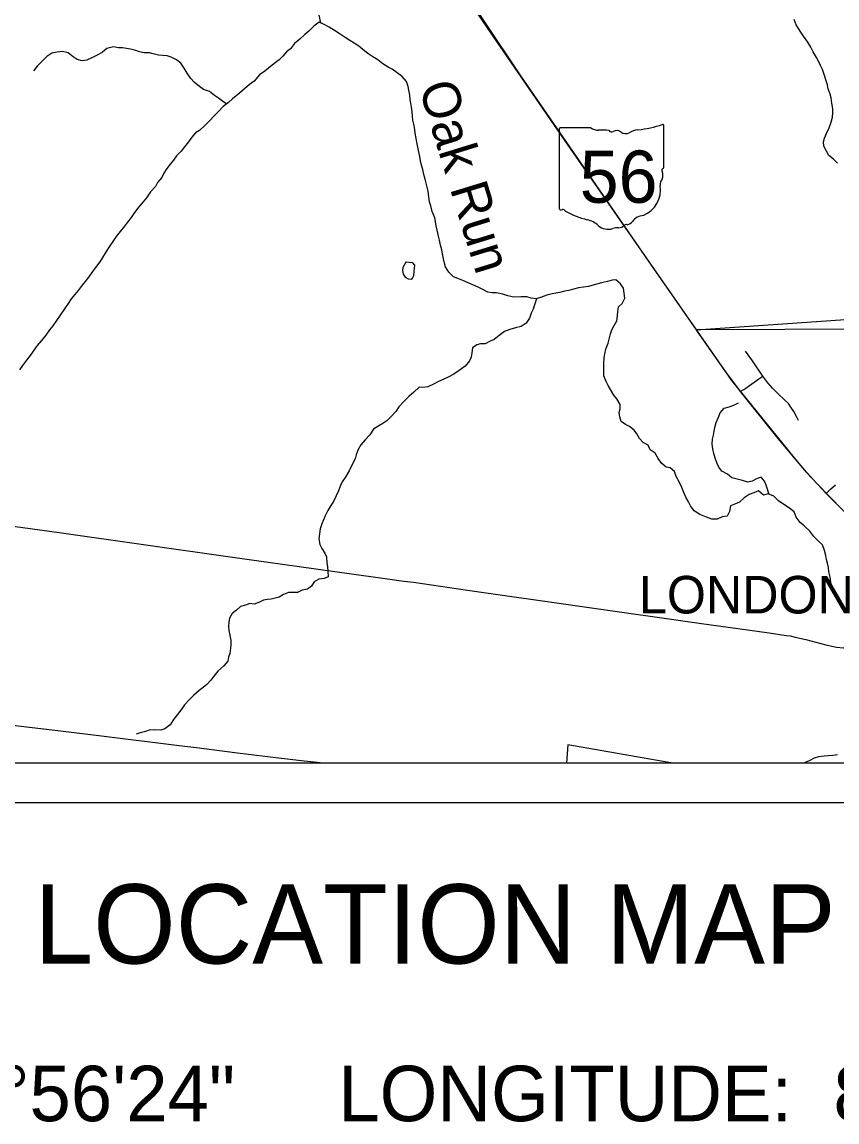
# Model space of a CAD drawing. Extents: x 0 to 36.5, y 0 to 25.3.
# Drawn here: x 4.396 to 6.451, y 13.194 to 15.97 of the extents above; entities that cross this region are included whole.
import ezdxf

# ---------------------------------------------------------------- set-up
doc = ezdxf.new("R2010")
doc.units = 0
for name, color, linetype in [('Default', 7, 'Continuous'), ('DV_X_Township_Line', 7, 'Continuous'), ('GM_X_City_Street', 7, 'Continuous'), ('GM_X_Corporation_Text', 7, 'Continuous'), ('GM_X_County_Road', 7, 'Continuous'), ('GM_X_Minor_Lake', 7, 'Continuous'), ('GM_X_Minor_River', 7, 'Continuous'), ('GM_X_Minor_River_Text', 7, 'Continuous'), ('GM_X_Rail_Line', 7, 'Continuous'), ('GM_X_State_Location', 7, 'Continuous'), ('GM_X_State_Route', 7, 'Continuous'), ('GM_X_State_Shield', 7, 'Continuous'), ('SH_Cut_Line', 7, 'Continuous'), ('SH_Data', 7, 'Continuous'), ('SH_Text', 7, 'Continuous')]:
    doc.layers.add(name, color=color, linetype=linetype)

msp = doc.modelspace()

# ---------------------------------------------------------------- linework, layer by layer
at = {"layer": 'Default'}
msp.add_lwpolyline([(5.7689, 14.1), (6.0321, 14.1), (5.7728, 14.1454)], close=True, dxfattribs=at)
at = {"layer": 'DV_X_Township_Line'}
msp.add_lwpolyline([(2.1, 16.2788), (2.1, 14.1), (8.9, 14.1), (8.9, 14.8674), (8.5228, 15.0526), (8.0723, 15.2737), (7.8139, 15.4027), (7.7814, 15.4189), (7.7552, 15.432), (7.703, 15.458), (6.8419, 15.8878), (6.6079, 15.9978), (5.1383, 16.6527), (4.8891, 16.7511), (4.0938, 16.595), (2.4938, 16.3413), (2.1039, 16.2931)], close=True, dxfattribs=at)
at = {"layer": 'GM_X_City_Street'}
for points in [[(6.354, 14.964), (6.3492, 14.9741), (6.342, 14.9872), (6.335, 14.9979), (6.3285, 15.0068), (6.3199, 15.0158), (6.3019, 15.0326), (6.2886, 15.0454), (6.2767, 15.0595), (6.2645, 15.0761), (6.2382, 15.1149), (6.2203, 15.1387)], [(6.2068, 15.0375), (6.2163, 15.0426), (6.2217, 15.046), (6.2308, 15.0522), (6.2541, 15.0694), (6.2645, 15.0761)], [(6.4241, 14.7802), (6.435, 14.7912), (6.4473, 14.8016)]]:
    msp.add_lwpolyline(points, dxfattribs=at)
at = {"layer": 'GM_X_County_Road'}
for points in [[(4.2393, 14.7169), (4.3059, 14.707), (4.4899, 14.6813), (4.9211, 14.6198), (5.227, 14.5775), (5.3061, 14.5659), (5.3593, 14.5586), (5.3831, 14.556), (5.5195, 14.5361), (6.104, 14.453), (6.2799, 14.4286), (6.3234, 14.4219), (6.333, 14.4203), (6.3453, 14.4176)], [(6.3453, 14.4176), (6.3727, 14.4112), (6.4231, 14.3979), (6.4497, 14.3921), (6.4678, 14.3903), (6.4858, 14.3904), (6.5038, 14.3924), (6.61, 14.4085)]]:
    msp.add_lwpolyline(points, dxfattribs=at)
at = {"layer": 'GM_X_Minor_Lake'}
for points in [[(5.3636, 15.3633), (5.3568, 15.3504), (5.3556, 15.3424), (5.3571, 15.3337), (5.362, 15.3257), (5.3703, 15.3215), (5.3791, 15.3207), (5.3805, 15.3233)], [(5.3805, 15.3233), (5.384, 15.3302), (5.3848, 15.3393), (5.386, 15.3476), (5.3868, 15.3564), (5.3815, 15.3621), (5.372, 15.3629), (5.3636, 15.3633)]]:
    msp.add_lwpolyline(points, dxfattribs=at)
at = {"layer": 'GM_X_Minor_River'}
for points in [[(5.4489, 15.4193), (5.4467, 15.4296), (5.443, 15.4441), (5.4401, 15.4555), (5.439, 15.4661), (5.4368, 15.4756), (5.4305, 15.4917), (5.4272, 15.5054), (5.4239, 15.5156), (5.4221, 15.5282), (5.4207, 15.5426), (5.4174, 15.5533), (5.4152, 15.5628), (5.4126, 15.5727), (5.4097, 15.5849), (5.4068, 15.5975), (5.4031, 15.6082), (5.4009, 15.6192), (5.3995, 15.6302), (5.3958, 15.6451), (5.3929, 15.6622), (5.3904, 15.6759), (5.3878, 15.6888), (5.3868, 15.6987), (5.3842, 15.7117), (5.3817, 15.7219), (5.381, 15.7318), (5.3799, 15.7432), (5.3781, 15.7546), (5.3763, 15.7645), (5.3753, 15.7744), (5.3742, 15.7847), (5.3713, 15.7973), (5.3695, 15.8068), (5.3658, 15.8197), (5.3545, 15.8324), (5.3421, 15.8412), (5.3296, 15.8508), (5.3194, 15.8555), (5.3062, 15.8643), (5.2937, 15.8739), (5.2805, 15.882), (5.2707, 15.8886), (5.2609, 15.8959), (5.2454, 15.9085), (5.2337, 15.9159), (5.2227, 15.9228), (5.211, 15.9305), (5.1986, 15.9393), (5.1838, 15.9482), (5.1706, 15.9567), (5.1585, 15.9632), (5.1452, 15.9694), (5.1322, 15.9589), (5.1192, 15.9469), (5.1093, 15.9378), (5.097, 15.9262), (5.0836, 15.9153), (5.0728, 15.9024), (5.0629, 15.8942), (5.0541, 15.8836), (5.0445, 15.8746), (5.0345, 15.867), (5.0185, 15.8539), (5.0081, 15.846), (4.9951, 15.8362), (4.9813, 15.8204), (4.9702, 15.8121), (4.9572, 15.8012), (4.9446, 15.7903), (4.9273, 15.7757), (4.9166, 15.7666), (4.9032, 15.7565), (4.8913, 15.7437), (4.8814, 15.7335), (4.8702, 15.7214), (4.8568, 15.7086), (4.8438, 15.6958), (4.8339, 15.6902), (4.8243, 15.6793), (4.8162, 15.6676), (4.8055, 15.6551), (4.7974, 15.6434), (4.7859, 15.6321), (4.7782, 15.6208), (4.7697, 15.6106), (4.7613, 15.6), (4.7536, 15.5879), (4.7489, 15.5773), (4.7382, 15.5649), (4.7324, 15.5543), (4.7201, 15.5415), (4.7105, 15.5264), (4.702, 15.5162), (4.6905, 15.5034), (4.6801, 15.489), (4.6717, 15.4766), (4.6624, 15.4645), (4.6547, 15.4547), (4.644, 15.4411), (4.6336, 15.4287)], [(5.1495, 15.9675), (5.1458, 15.9869)], [(6.4521, 15.6131), (6.442, 15.6238), (6.4303, 15.6331), (6.4243, 15.6434), (6.4183, 15.6563), (6.4169, 15.6674), (6.4196, 15.6768), (6.4243, 15.6882), (6.4316, 15.7026), (6.4363, 15.717), (6.4399, 15.7299), (6.4411, 15.7401), (6.4404, 15.7508), (6.4383, 15.7652), (6.4365, 15.7781), (6.4339, 15.788), (6.4287, 15.8014), (6.4273, 15.8109), (6.4232, 15.8239), (6.4199, 15.8349), (6.4143, 15.8501), (6.4095, 15.8597), (6.4054, 15.8692), (6.3994, 15.8799), (6.3908, 15.8941), (6.3856, 15.9059), (6.3773, 15.9192), (6.3668, 15.9338), (6.3597, 15.9437), (6.3545, 15.9533), (6.3485, 15.9628), (6.3429, 15.9758)], [(4.9119, 15.7631), (4.9049, 15.7675), (4.892, 15.7775), (4.8818, 15.7844), (4.8686, 15.794), (4.8542, 15.7995), (4.8436, 15.8068), (4.8301, 15.8179), (4.8222, 15.8275), (4.8128, 15.8405), (4.8053, 15.8535), (4.7963, 15.8657), (4.7857, 15.8741), (4.7725, 15.8811), (4.7623, 15.8846), (4.7513, 15.8855), (4.7403, 15.8863), (4.727, 15.8895), (4.7175, 15.8918), (4.7046, 15.8923), (4.6928, 15.8947), (4.6834, 15.8974), (4.6701, 15.9014), (4.6595, 15.903), (4.6492, 15.9046), (4.6397, 15.9047), (4.6272, 15.9071), (4.6101, 15.9026), (4.599, 15.8932), (4.5871, 15.8865), (4.5738, 15.8798), (4.56, 15.8738), (4.5475, 15.8713), (4.535, 15.8748), (4.5248, 15.8821), (4.5123, 15.8921), (4.4983, 15.8956), (4.4846, 15.8935), (4.4713, 15.8909), (4.4587, 15.8823), (4.448, 15.8721), (4.4341, 15.8582), (4.4253, 15.8465)], [(4.6336, 15.4287), (4.6271, 15.4181), (4.6163, 15.4022), (4.6082, 15.3909), (4.5993, 15.3754), (4.5928, 15.3648), (4.5816, 15.3501), (4.5739, 15.3399), (4.5651, 15.327), (4.5551, 15.315), (4.5478, 15.3052), (4.5378, 15.2919), (4.5293, 15.2818), (4.5201, 15.2708), (4.5128, 15.2595), (4.5036, 15.2455), (4.4924, 15.2297), (4.4828, 15.2168), (4.4736, 15.2028), (4.4659, 15.1927), (4.4562, 15.1791), (4.4451, 15.1662), (4.4344, 15.153), (4.4247, 15.1387), (4.417, 15.1285), (4.4078, 15.116), (4.3971, 15.1032), (4.3901, 15.0922)], [(6.1799, 14.7348), (6.1741, 14.7227), (6.1619, 14.7213), (6.149, 14.7153), (6.136, 14.715), (6.1224, 14.7205), (6.105, 14.7271), (6.0914, 14.7359), (6.082, 14.7486), (6.0764, 14.7585), (6.0712, 14.7688), (6.0652, 14.7825), (6.0596, 14.7951), (6.0533, 14.8092), (6.0454, 14.8226), (6.0414, 14.8355), (6.0304, 14.8444), (6.0202, 14.8464), (6.0092, 14.8556), (5.9999, 14.8682), (5.9928, 14.8819), (5.9799, 14.89), (5.9747, 14.9022), (5.9622, 14.9084), (5.9536, 14.9184), (5.9465, 14.9306), (5.9401, 14.9401), (5.928, 14.949), (5.9182, 14.9536), (5.9072, 14.9617), (5.9039, 14.9731), (5.9021, 14.9842), (5.9041, 14.9936), (5.9042, 15.0043), (5.8959, 15.0184), (5.8888, 15.028), (5.8798, 15.0425), (5.8738, 15.0528), (5.869, 15.0623), (5.8634, 15.0764), (5.8631, 15.0859), (5.8633, 15.108), (5.8638, 15.1228), (5.867, 15.1368), (5.8693, 15.1467), (5.8744, 15.1592), (5.8775, 15.1728), (5.8799, 15.1827), (5.8834, 15.1929), (5.8892, 15.2042), (5.8958, 15.216), (5.8978, 15.2285), (5.8987, 15.2391), (5.9003, 15.2509), (5.9098, 15.2592), (5.9161, 15.2728), (5.9143, 15.2857), (5.9132, 15.2983), (5.9057, 15.3086), (5.8937, 15.3189), (5.8842, 15.3183), (5.8723, 15.3149), (5.8575, 15.3117), (5.848, 15.3087), (5.8385, 15.3061), (5.8247, 15.3024), (5.8122, 15.3007), (5.7996, 15.2992), (5.7867, 15.2952), (5.7753, 15.2922), (5.7642, 15.2901), (5.752, 15.2875), (5.7425, 15.2853), (5.733, 15.2839), (5.7193, 15.2802), (5.706, 15.275), (5.6923, 15.2713), (5.6801, 15.2729), (5.6695, 15.2761), (5.6551, 15.2762), (5.6361, 15.2756), (5.6216, 15.2784), (5.6084, 15.283), (5.5928, 15.2862), (5.5818, 15.2863), (5.5708, 15.2883), (5.5568, 15.2956), (5.5466, 15.3007), (5.533, 15.3065), (5.5213, 15.3112), (5.5076, 15.317), (5.4955, 15.3228), (5.4845, 15.3263), (5.4721, 15.3386), (5.4642, 15.3515), (5.4617, 15.3614), (5.4591, 15.3717), (5.4566, 15.3847), (5.4547, 15.3949), (5.4518, 15.4064), (5.4489, 15.4193)], [(5.6932, 15.2715), (5.6887, 15.2558), (5.6848, 15.2451), (5.6802, 15.2349), (5.6755, 15.2224), (5.6674, 15.21), (5.6544, 15.2013), (5.6403, 15.1977), (5.6262, 15.1936), (5.6125, 15.1888), (5.5995, 15.179), (5.5869, 15.1689), (5.5769, 15.1644), (5.5643, 15.1573), (5.5526, 15.1578), (5.543, 15.1552), (5.5323, 15.1473), (5.5303, 15.1348), (5.5287, 15.1242), (5.5248, 15.1143), (5.5137, 15.1015), (5.4984, 15.0906), (5.485, 15.0809), (5.4705, 15.0734), (5.4595, 15.0685), (5.4461, 15.0622), (5.4335, 15.0562), (5.4198, 15.0491), (5.4068, 15.0477), (5.3973, 15.0478), (5.3839, 15.0354), (5.3713, 15.0245), (5.359, 15.012), (5.3467, 14.9985), (5.3387, 14.9864), (5.3272, 14.9739), (5.3157, 14.9634), (5.3061, 14.9563), (5.2958, 14.951), (5.2828, 14.942), (5.2732, 14.9281), (5.2617, 14.9152), (5.2505, 14.9028), (5.2428, 14.8892), (5.2385, 14.8775), (5.2362, 14.8672), (5.2288, 14.8528), (5.2211, 14.8373), (5.2126, 14.8226), (5.2037, 14.8094), (5.1987, 14.7988), (5.194, 14.7863), (5.1882, 14.7742), (5.1816, 14.7598), (5.1747, 14.7496), (5.167, 14.7367), (5.1608, 14.7235), (5.1562, 14.7137), (5.1519, 14.7034), (5.1484, 14.6909), (5.146, 14.678), (5.1447, 14.6651), (5.1469, 14.6514), (5.1525, 14.6415), (5.1596, 14.6293), (5.1637, 14.6198), (5.1651, 14.6053), (5.1665, 14.5954), (5.1675, 14.5829), (5.1682, 14.5692), (5.1583, 14.5651), (5.1449, 14.5633), (5.1327, 14.5566), (5.1258, 14.546), (5.1159, 14.5389), (5.1025, 14.5363), (5.0907, 14.53), (5.0679, 14.5302), (5.0557, 14.5253), (5.045, 14.5186), (5.0343, 14.516), (5.0244, 14.5134), (5.0149, 14.5124), (5.005, 14.5106), (4.9951, 14.5053), (4.9818, 14.5009), (4.9704, 14.5021), (4.9601, 14.4984), (4.9471, 14.4944), (4.9368, 14.4857), (4.9265, 14.4767), (4.9192, 14.4657), (4.9179, 14.4559), (4.9171, 14.4441), (4.9177, 14.4338), (4.9203, 14.4228), (4.9228, 14.4091), (4.9227, 14.3992), (4.9223, 14.3897), (4.9203, 14.3761), (4.9171, 14.3666)], [(6.279, 14.7787), (6.2758, 14.7909), (6.2724, 14.8008), (6.2683, 14.8111), (6.2597, 14.8211), (6.2502, 14.8181), (6.2376, 14.811), (6.2265, 14.8088), (6.2129, 14.8124), (6.1992, 14.8163), (6.186, 14.8198), (6.1747, 14.8283), (6.1607, 14.8364), (6.1535, 14.846), (6.1487, 14.8559), (6.1442, 14.8688), (6.1409, 14.8806), (6.1384, 14.8924), (6.1362, 14.9042), (6.1374, 14.9168), (6.1394, 14.927), (6.1418, 14.9376), (6.1442, 14.9498), (6.1469, 14.9592), (6.152, 14.9725), (6.157, 14.9838), (6.167, 14.9951), (6.1792, 14.9988), (6.191, 15.0025), (6.2028, 15.0085)], [(6.453, 14.5113), (6.4467, 14.5243), (6.443, 14.5353), (6.4381, 14.5456), (6.4359, 14.5559), (6.4337, 14.5684), (6.4308, 14.5825), (6.4294, 14.5932), (6.4272, 14.6038), (6.425, 14.6137), (6.4232, 14.6236), (6.4199, 14.6362), (6.4143, 14.6507), (6.4045, 14.6595), (6.3929, 14.671), (6.3823, 14.6848), (6.3688, 14.6982), (6.3586, 14.7066), (6.3481, 14.72), (6.3429, 14.7334), (6.3316, 14.743), (6.3172, 14.7522), (6.3036, 14.7618), (6.2919, 14.7733), (6.2779, 14.7791), (6.2661, 14.7758), (6.2533, 14.7862), (6.2419, 14.7814), (6.2297, 14.7777), (6.2174, 14.7687), (6.2052, 14.7581), (6.1956, 14.754), (6.1827, 14.7488), (6.1799, 14.7348)], [(4.9171, 14.3666), (4.9148, 14.3571), (4.9048, 14.345), (4.8899, 14.3315), (4.8795, 14.319), (4.8726, 14.3088), (4.8622, 14.2983), (4.8526, 14.2904), (4.8427, 14.2825), (4.8293, 14.2708), (4.8186, 14.2599), (4.8063, 14.2467), (4.799, 14.2365), (4.7882, 14.2226), (4.7786, 14.2094), (4.7697, 14.1958), (4.7564, 14.1864), (4.7461, 14.183), (4.7301, 14.1839), (4.7168, 14.1825), (4.7073, 14.1792), (4.694, 14.1763), (4.6837, 14.1726)], [(6.4522, 14.1207), (6.4404, 14.1186), (6.4301, 14.1175), (6.4187, 14.1168), (6.4043, 14.1158), (6.3932, 14.1117), (6.381, 14.1054), (6.3711, 14.1013), (6.3689, 14.1)]]:
    msp.add_lwpolyline(points, dxfattribs=at)
at = {"layer": 'GM_X_Rail_Line'}
for points in [[(4.8132, 17.3633), (4.8184, 17.2699), (5.1178, 16.6892), (5.2481, 16.4408), (5.283, 16.3883), (5.6533, 15.8339), (5.9752, 15.3666), (6.1855, 15.065), (6.3543, 14.8564), (6.3992, 14.8058), (6.6962, 14.5011), (6.7726, 14.421), (6.8941, 14.2837), (7.0545, 14.1)], [(2.9959, 14.3635), (3.2993, 14.3271), (3.4345, 14.31), (3.6331, 14.2857), (3.7599, 14.2703), (3.8768, 14.2559), (3.9653, 14.2449), (4.0847, 14.2307), (4.1319, 14.225), (4.2195, 14.2143), (4.28, 14.2068), (4.3249, 14.2011), (4.3358, 14.1998), (4.4011, 14.1918), (4.4931, 14.1806), (4.5963, 14.1681), (4.7925, 14.1443), (4.836, 14.139), (4.9328, 14.1267), (5.0153, 14.1165), (5.1077, 14.1057), (5.1561, 14.1)]]:
    msp.add_lwpolyline(points, dxfattribs=at)
at = {"layer": 'GM_X_State_Route'}
for p, q in [((6.0961, 15.1927), (6.0988, 15.1888)), ((6.4276, 14.7766), (6.4617, 14.7421))]:
    msp.add_line(p, q, dxfattribs=at)
for points in [[(5.2509, 16.4373), (5.2534, 16.4329), (5.5332, 16.0079), (5.5924, 15.9207), (5.7648, 15.6702), (6.0961, 15.1927)], [(6.0988, 15.1888), (6.1715, 15.084), (6.1898, 15.06)], [(6.1898, 15.06), (6.2068, 15.0375), (6.3021, 14.9187), (6.3457, 14.8663), (6.3738, 14.8336), (6.4036, 14.8016), (6.4241, 14.7802), (6.4276, 14.7766)]]:
    msp.add_lwpolyline(points, dxfattribs=at)
at = {"layer": 'GM_X_State_Shield'}
for p, q in [((5.7509, 15.6995), (5.7509, 15.4994)), ((5.8307, 15.703), (5.7535, 15.703)), ((6.0145, 15.6032), (6.0145, 15.7079)), ((6.0145, 15.6033), (6.0145, 15.6032))]:
    msp.add_line(p, q, dxfattribs=at)
for centre, radius, start, end in [((5.9206, 15.9758), 0.2796, 275.8445, 288.9065), ((6.0116, 15.7084), 0.00294, 351.8621, 97.738), ((5.7539, 15.6999), 0.00305, 98.1301, 188.1301), ((5.8491, 15.7262), 0.0296, 231.6195, 271.1119), ((5.8589, 15.5906), 0.1064, 80.4867, 94.9883), ((5.8831, 15.701), 0.00855, 219.7921, 297.1024), ((5.8956, 15.6779), 0.0178, 54.4667, 119.1411), ((5.9185, 15.7096), 0.0214, 233.8562, 294.8282), ((5.9563, 15.6418), 0.0563, 97.3462, 120.7689), ((6.0114, 15.6028), 0.00314, 289.6038, 7.7341), ((6.0251, 15.5594), 0.0198, 136.8065, 186.9296), ((6.0139, 15.5955), 0.00454, 107.944, 210.337), ((5.985, 15.5823), 0.0273, 340.033, 23.6496), ((5.9363, 15.5461), 0.0699, 292.3089, 8.9858), ((5.7539, 15.499), 0.00308, 171.9584, 258.3066), ((5.7544, 15.5194), 0.0235, 267.339, 280.6039), ((5.7592, 15.4879), 0.00848, 29.7484, 93.2717), ((5.8663, 15.6677), 0.2019, 240.4129, 257.1985), ((5.8061, 15.4095), 0.0632, 47.1842, 75.836), ((5.9173, 15.48), 0.0226, 282.8732, 323.2771), ((5.9658, 15.4432), 0.0383, 94.4031, 142.5768), ((5.8744, 15.4869), 0.0401, 230.7004, 286.2918), ((5.8976, 15.4177), 0.0329, 85.6951, 111.2099), ((5.9005, 15.4719), 0.0214, 268.777, 315.5493), ((5.9198, 15.4525), 0.00601, 65.7517, 132.6484)]:
    msp.add_arc(centre, radius, start, end, dxfattribs=at)
at = {"layer": 'SH_Cut_Line'}
msp.add_lwpolyline([(4.4591, 20.9), (3.3366, 20.9), (3.2612, 20.6041), (2.8463, 19.037), (2.6265, 18.2595), (2.5271, 17.8912), (2.5226, 17.8751), (2.5165, 17.8524), (2.5144, 17.8445), (2.4192, 17.4891), (2.3437, 17.2326), (2.3403, 17.2198), (2.1039, 16.2931), (2.1, 16.2788), (2.1, 14.1), (8.9, 14.1), (8.9, 20.9), (6.1845, 20.9)], dxfattribs=at)
at = {"layer": 'SH_Data'}
for p, q in [((2.1, 14.1), (8.9, 14.1)), ((2, 14), (9, 14))]:
    msp.add_line(p, q, dxfattribs=at)
msp.add_lwpolyline([(5.2509, 16.4373), (5.2534, 16.4329), (5.5332, 16.0079), (5.5924, 15.9207), (5.7648, 15.6702), (6.0961, 15.1927)], dxfattribs=at)
at = {"layer": 'SH_Text'}
msp.add_lwpolyline([(6.0961, 15.1927), (9.2246, 15.4103), (9.2246, 15.2045)], close=True, dxfattribs=at)

# ---------------------------------------------------------------- texts
at = {"layer": 'GM_X_Corporation_Text'}
msp.add_text('LONDON', height=0.0947, rotation=0, dxfattribs=at).set_placement((5.9518, 14.4772))
at = {"layer": 'GM_X_Minor_River_Text'}
msp.add_text('Oak Run', height=0.09468, rotation=287.0918, dxfattribs=at).set_placement((5.3959, 15.806))
at = {"layer": 'GM_X_State_Location'}
msp.add_text('56', height=0.000189, rotation=0, dxfattribs=at).set_placement((5.9793, 15.299))
for s in ['s', 'r']:
    msp.add_text(s, height=0.000189, dxfattribs=at).set_placement((6.027, 15.3128))
at = {"layer": 'GM_X_State_Shield'}
msp.add_text('56', height=0.13184, dxfattribs=at).set_placement((5.8024, 15.5135))
at = {"layer": 'SH_Text'}
for s, height, p in [('LOCATION MAP', 0.2, (4.4269, 13.5938)), ('LATITUDE:  39°56\'24"     LONGITUDE:  83°29\'52"', 0.14, (3.071, 13.1959))]:
    msp.add_text(s, height=height, dxfattribs=at).set_placement(p)

doc.saveas('drawing.dxf')
